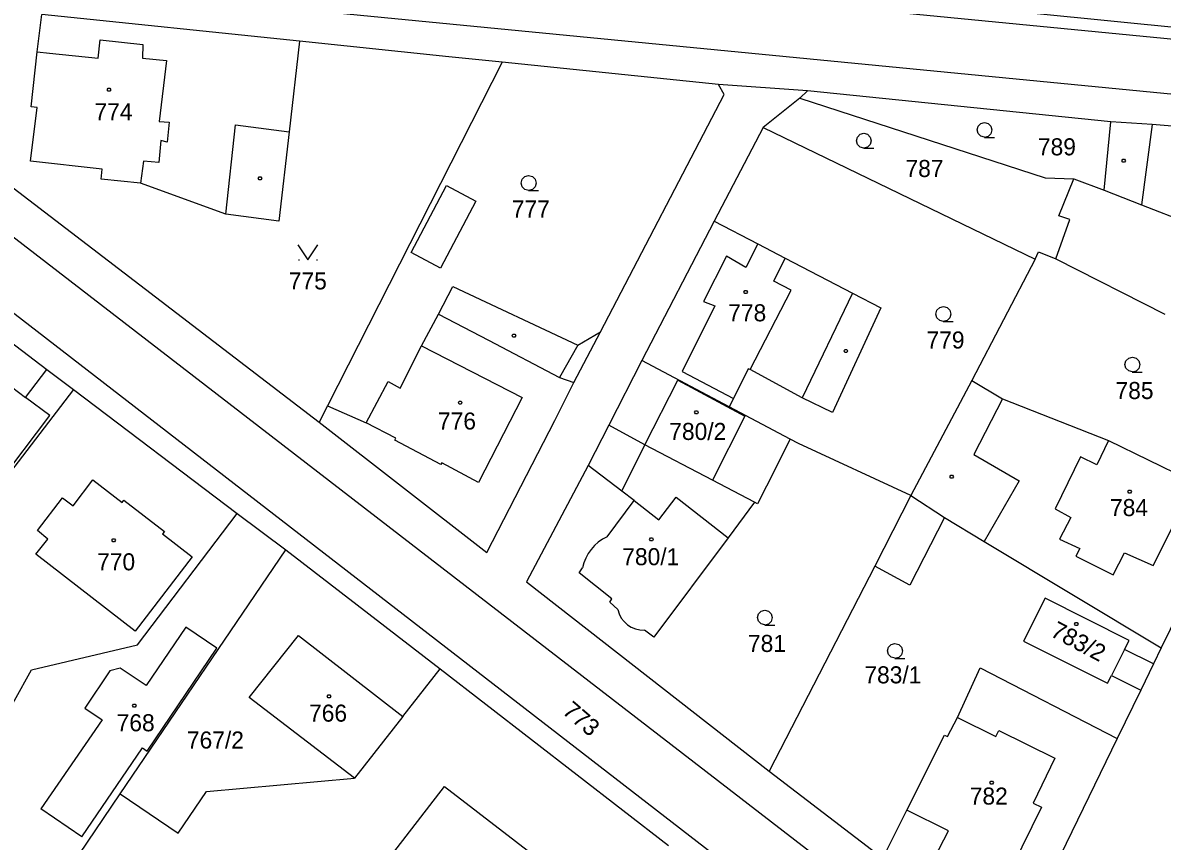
# Model space of a CAD drawing. Extents: x -621797 to -620972, y -1175539 to -1174697.
# Drawn here: x -621205.7 to -621092, y -1175212.1 to -1175130.5 of the extents above; entities that cross this region are included whole.
import ezdxf

# ---------------------------------------------------------------- set-up
doc = ezdxf.new("R2010")
doc.units = 0
for name, color, linetype in [('Rozvod plynu EON', 7, 'Continuous'), ('SDEL EON', 7, 'Continuous'), ('SDEL EON - popis', 7, 'Continuous'), ('Silnoproud EON', 7, 'Continuous'), ('Silnoproud EON - popis', 7, 'Continuous')]:
    doc.layers.add(name, color=color, linetype=linetype)

msp = doc.modelspace()

# ---------------------------------------------------------------- linework, layer by layer
at = {"layer": 'Rozvod plynu EON'}
for points in [[(-621196.98, -1175137.07), (-621196.89, -1175137.22), (-621196.98, -1175137.37), (-621197.16, -1175137.37), (-621197.25, -1175137.22), (-621197.16, -1175137.07)], [(-621095.77, -1175144.15), (-621095.68, -1175144.3), (-621095.77, -1175144.45), (-621095.95, -1175144.45), (-621096.04, -1175144.3), (-621095.95, -1175144.15)], [(-621181.93, -1175145.91), (-621181.84, -1175146.06), (-621181.93, -1175146.21), (-621182.11, -1175146.21), (-621182.2, -1175146.06), (-621182.11, -1175145.91)], [(-621133.48, -1175157.24), (-621133.39, -1175157.39), (-621133.48, -1175157.54), (-621133.66, -1175157.54), (-621133.75, -1175157.39), (-621133.66, -1175157.24)], [(-621156.6, -1175161.58), (-621156.51, -1175161.73), (-621156.6, -1175161.88), (-621156.78, -1175161.88), (-621156.87, -1175161.73), (-621156.78, -1175161.58)], [(-621123.49, -1175163.11), (-621123.4, -1175163.26), (-621123.49, -1175163.41), (-621123.67, -1175163.41), (-621123.76, -1175163.26), (-621123.67, -1175163.11)], [(-621161.96, -1175168.28), (-621161.87, -1175168.43), (-621161.96, -1175168.58), (-621162.14, -1175168.58), (-621162.23, -1175168.43), (-621162.14, -1175168.28)], [(-621138.39, -1175169.23), (-621138.3, -1175169.38), (-621138.39, -1175169.53), (-621138.57, -1175169.53), (-621138.66, -1175169.38), (-621138.57, -1175169.23)], [(-621112.94, -1175175.66), (-621112.85, -1175175.81), (-621112.94, -1175175.96), (-621113.12, -1175175.96), (-621113.21, -1175175.81), (-621113.12, -1175175.66)], [(-621095.19, -1175177.13), (-621095.1, -1175177.28), (-621095.19, -1175177.43), (-621095.37, -1175177.43), (-621095.46, -1175177.28), (-621095.37, -1175177.13)], [(-621196.52, -1175181.99), (-621196.43, -1175182.14), (-621196.52, -1175182.29), (-621196.7, -1175182.29), (-621196.79, -1175182.14), (-621196.7, -1175181.99)], [(-621142.88, -1175181.9), (-621142.79, -1175182.05), (-621142.88, -1175182.2), (-621143.06, -1175182.2), (-621143.15, -1175182.05), (-621143.06, -1175181.9)], [(-621100.5, -1175190.35), (-621100.41, -1175190.5), (-621100.5, -1175190.65), (-621100.68, -1175190.65), (-621100.77, -1175190.5), (-621100.68, -1175190.35)], [(-621175.04, -1175197.57), (-621174.95, -1175197.72), (-621175.04, -1175197.87), (-621175.22, -1175197.87), (-621175.31, -1175197.72), (-621175.22, -1175197.57)], [(-621194.45, -1175198.48), (-621194.36, -1175198.63), (-621194.45, -1175198.78), (-621194.63, -1175198.78), (-621194.72, -1175198.63), (-621194.63, -1175198.48)], [(-621108.95, -1175206.16), (-621108.86, -1175206.31), (-621108.95, -1175206.46), (-621109.13, -1175206.46), (-621109.22, -1175206.31), (-621109.13, -1175206.16)]]:
    msp.add_lwpolyline(points, close=True, dxfattribs=at)
at = {"layer": 'SDEL EON'}
for p, q in [((-621178.19, -1175154.18), (-621178.09, -1175154.18)), ((-621176.39, -1175154.18), (-621176.29, -1175154.18))]:
    msp.add_line(p, q, dxfattribs=at)
for points in [[(-621109.74, -1175141.96), (-621110.12, -1175141.86), (-621110.39, -1175141.59), (-621110.49, -1175141.22), (-621110.39, -1175140.85), (-621110.12, -1175140.58), (-621109.75, -1175140.48), (-621109.38, -1175140.58), (-621109.11, -1175140.85), (-621109.01, -1175141.23), (-621109.11, -1175141.61), (-621109.38, -1175141.88), (-621109.76, -1175141.98), (-621108.76, -1175141.98)], [(-621121.78, -1175143.04), (-621122.16, -1175142.94), (-621122.43, -1175142.67), (-621122.53, -1175142.3), (-621122.43, -1175141.93), (-621122.16, -1175141.66), (-621121.79, -1175141.56), (-621121.42, -1175141.66), (-621121.15, -1175141.93), (-621121.05, -1175142.31), (-621121.15, -1175142.69), (-621121.42, -1175142.96), (-621121.8, -1175143.06), (-621120.8, -1175143.06)], [(-621155.21, -1175147.26), (-621155.59, -1175147.16), (-621155.86, -1175146.89), (-621155.96, -1175146.52), (-621155.86, -1175146.15), (-621155.59, -1175145.88), (-621155.22, -1175145.78), (-621154.85, -1175145.88), (-621154.58, -1175146.15), (-621154.48, -1175146.53), (-621154.58, -1175146.91), (-621154.85, -1175147.18), (-621155.23, -1175147.28), (-621154.23, -1175147.28)], [(-621178.24, -1175152.68), (-621177.24, -1175154.18), (-621176.24, -1175152.68)], [(-621113.84, -1175160.32), (-621114.22, -1175160.22), (-621114.49, -1175159.95), (-621114.59, -1175159.58), (-621114.49, -1175159.21), (-621114.22, -1175158.94), (-621113.85, -1175158.84), (-621113.48, -1175158.94), (-621113.21, -1175159.21), (-621113.11, -1175159.59), (-621113.21, -1175159.97), (-621113.48, -1175160.24), (-621113.86, -1175160.34), (-621112.86, -1175160.34)], [(-621094.99, -1175165.36), (-621095.37, -1175165.26), (-621095.64, -1175164.99), (-621095.74, -1175164.62), (-621095.64, -1175164.25), (-621095.37, -1175163.98), (-621095, -1175163.88), (-621094.63, -1175163.98), (-621094.36, -1175164.25), (-621094.26, -1175164.63), (-621094.36, -1175165.01), (-621094.63, -1175165.28), (-621095.01, -1175165.38), (-621094.01, -1175165.38)], [(-621131.65, -1175190.58), (-621132.03, -1175190.48), (-621132.3, -1175190.21), (-621132.4, -1175189.84), (-621132.3, -1175189.47), (-621132.03, -1175189.2), (-621131.66, -1175189.1), (-621131.29, -1175189.2), (-621131.02, -1175189.47), (-621130.92, -1175189.85), (-621131.02, -1175190.23), (-621131.29, -1175190.5), (-621131.67, -1175190.6), (-621130.67, -1175190.6)], [(-621118.67, -1175193.91), (-621119.05, -1175193.81), (-621119.32, -1175193.54), (-621119.42, -1175193.17), (-621119.32, -1175192.8), (-621119.05, -1175192.53), (-621118.68, -1175192.43), (-621118.31, -1175192.53), (-621118.04, -1175192.8), (-621117.94, -1175193.18), (-621118.04, -1175193.56), (-621118.31, -1175193.83), (-621118.69, -1175193.93), (-621117.69, -1175193.93)]]:
    msp.add_lwpolyline(points, dxfattribs=at)
at = {"layer": 'SDEL EON - popis'}
for p, q in [((-621197.6, -1175121.77), (-621081.88, -1175133.05)), ((-621082.31, -1175138.52), (-621199.05, -1175127.17)), ((-621198.16, -1175134.08), (-621197.97, -1175132.25)), ((-621197.97, -1175132.25), (-621193.69, -1175132.7)), ((-621204.25, -1175133.44), (-621203, -1175133.57)), ((-621193.69, -1175132.7), (-621193.74, -1175134.06)), ((-621203, -1175133.57), (-621198.16, -1175134.08)), ((-621193.74, -1175134.06), (-621191.34, -1175134.31)), ((-621191.34, -1175134.31), (-621192.06, -1175140.38)), ((-621192.06, -1175140.38), (-621191.08, -1175140.46)), ((-621191.08, -1175140.46), (-621191.28, -1175142.45)), ((-621185.43, -1175149.61), (-621184.45, -1175140.72)), ((-621184.45, -1175140.72), (-621179.09, -1175141.41)), ((-621093.04, -1175140.67), (-621094.1, -1175148.7)), ((-621191.92, -1175142.28), (-621192.12, -1175144.47)), ((-621191.28, -1175142.45), (-621191.92, -1175142.28)), ((-621193.62, -1175144.34), (-621193.93, -1175146.55)), ((-621192.12, -1175144.47), (-621193.62, -1175144.34)), ((-621166.95, -1175153.44), (-621163.42, -1175146.78)), ((-621163.42, -1175146.78), (-621160.48, -1175148.34)), ((-621160.48, -1175148.34), (-621164.01, -1175155)), ((-621208, -1175150.85), (-621101.85, -1175232.68)), ((-621132.35, -1175152.58), (-621133.54, -1175154.94)), ((-621164.01, -1175155), (-621166.95, -1175153.44)), ((-621135.5, -1175153.8), (-621137.78, -1175158.33)), ((-621133.54, -1175154.94), (-621135.5, -1175153.8)), ((-621130.77, -1175156.32), (-621129.62, -1175154.01)), ((-621089.77, -1175249.76), (-621211.57, -1175155.68)), ((-621133.12, -1175165.13), (-621129.03, -1175157.19)), ((-621129.03, -1175157.19), (-621130.77, -1175156.32)), ((-621137.78, -1175158.33), (-621136.64, -1175158.77)), ((-621122.92, -1175157.49), (-621127.94, -1175167.95)), ((-621164.22, -1175159.59), (-621159.23, -1175162.19)), ((-621136.64, -1175158.77), (-621139.92, -1175165.3)), ((-621165.91, -1175162.75), (-621155.88, -1175167.92)), ((-621159.23, -1175162.19), (-621152.13, -1175165.9)), ((-621150.31, -1175162.69), (-621152.13, -1175165.9)), ((-621211.01, -1175163.66), (-621205.39, -1175167.9)), ((-621205.39, -1175167.9), (-621203.27, -1175165.11)), ((-621139.92, -1175165.3), (-621134.8, -1175167.99)), ((-621152.13, -1175165.9), (-621150.71, -1175166.41)), ((-621143.62, -1175172.63), (-621140.35, -1175166.18)), ((-621140.35, -1175166.18), (-621133.67, -1175169.76)), ((-621202.99, -1175169.71), (-621205.39, -1175167.9)), ((-621155.88, -1175167.92), (-621160.21, -1175176.39)), ((-621107.97, -1175168.05), (-621110.83, -1175173.59)), ((-621210.34, -1175179.44), (-621202.99, -1175169.71)), ((-621133.67, -1175169.76), (-621136.87, -1175176.14)), ((-621168.46, -1175171.97), (-621171.43, -1175170.44)), ((-621168.55, -1175172.16), (-621168.46, -1175171.97)), ((-621163.99, -1175174.6), (-621168.55, -1175172.16)), ((-621145.94, -1175177.23), (-621143.62, -1175172.63)), ((-621097.38, -1175172.19), (-621098.56, -1175174.62)), ((-621163.88, -1175174.41), (-621163.99, -1175174.6)), ((-621160.21, -1175176.39), (-621163.88, -1175174.41)), ((-621110.83, -1175173.59), (-621106.3, -1175176.2)), ((-621100.18, -1175173.83), (-621102.7, -1175179.02)), ((-621098.56, -1175174.62), (-621100.18, -1175173.83)), ((-621106.3, -1175176.2), (-621109.79, -1175182.26)), ((-621144.69, -1175178.19), (-621142.22, -1175180.12)), ((-621142.22, -1175180.12), (-621140.52, -1175177.86)), ((-621140.52, -1175177.86), (-621135.33, -1175181.89)), ((-621113.74, -1175179.87), (-621117.21, -1175186.62)), ((-621102.7, -1175179.02), (-621101.13, -1175179.87)), ((-621101.13, -1175179.87), (-621102.26, -1175182.04)), ((-621092.93, -1175184.65), (-621091.04, -1175180.89)), ((-621102.26, -1175182.04), (-621100.25, -1175182.96)), ((-621100.25, -1175182.96), (-621100.63, -1175183.74)), ((-621096.92, -1175185.58), (-621095.8, -1175183.39)), ((-621095.8, -1175183.39), (-621092.93, -1175184.65)), ((-621100.63, -1175183.74), (-621096.92, -1175185.58)), ((-621117.21, -1175186.62), (-621120.69, -1175184.73)), ((-621095.78, -1175193.04), (-621097.09, -1175195.62)), ((-621112.43, -1175199.81), (-621108.61, -1175201.7)), ((-621108.61, -1175201.7), (-621108.31, -1175201.12)), ((-621108.31, -1175201.12), (-621102.72, -1175203.88)), ((-621102.72, -1175203.88), (-621104.9, -1175208.35)), ((-621104.9, -1175208.35), (-621104.06, -1175208.76)), ((-621113.35, -1175211.13), (-621117.5, -1175209.07)), ((-621104.06, -1175208.76), (-621107.98, -1175216.73)), ((-621114.77, -1175213.88), (-621113.35, -1175211.13))]:
    msp.add_line(p, q, dxfattribs=at)
at = {"layer": 'Silnoproud EON'}
for p, q in [((-621147.63, -1175125.29), (-621085.82, -1175131.48)), ((-621204.25, -1175133.44), (-621203.79, -1175129.72)), ((-621178.07, -1175132.39), (-621203.79, -1175129.72)), ((-621204.83, -1175138.91), (-621204.25, -1175133.44)), ((-621178.07, -1175132.39), (-621179.09, -1175141.41)), ((-621163.19, -1175133.92), (-621178.07, -1175132.39)), ((-621157.87, -1175134.47), (-621175.27, -1175168.73)), ((-621157.87, -1175134.47), (-621163.19, -1175133.92)), ((-621136.29, -1175136.69), (-621157.87, -1175134.47)), ((-621127.39, -1175137.34), (-621136.29, -1175136.69)), ((-621135.71, -1175137.7), (-621136.29, -1175136.69)), ((-621148.06, -1175161.35), (-621135.71, -1175137.7)), ((-621127.39, -1175137.34), (-621128.18, -1175138.06)), ((-621097.16, -1175140.41), (-621127.39, -1175137.34)), ((-621204.91, -1175144.35), (-621204.25, -1175138.98)), ((-621204.25, -1175138.98), (-621204.83, -1175138.91)), ((-621128.18, -1175138.06), (-621131.84, -1175140.97)), ((-621128.18, -1175138.06), (-621103.71, -1175146)), ((-621179.09, -1175141.41), (-621180.14, -1175150.33)), ((-621131.84, -1175140.97), (-621136.7, -1175150.32)), ((-621131.84, -1175140.97), (-621104.71, -1175154.11)), ((-621097.83, -1175147.23), (-621097.16, -1175140.41)), ((-621093.04, -1175140.67), (-621097.16, -1175140.41)), ((-621072.86, -1175142.5), (-621093.04, -1175140.67)), ((-621213.76, -1175141.57), (-621176.1, -1175170.37)), ((-621197.76, -1175145.13), (-621204.91, -1175144.35)), ((-621197.87, -1175146.14), (-621197.76, -1175145.13)), ((-621103.71, -1175146), (-621100.85, -1175146.09)), ((-621193.93, -1175146.55), (-621197.87, -1175146.14)), ((-621185.43, -1175149.61), (-621193.93, -1175146.55)), ((-621102.32, -1175149.8), (-621100.85, -1175146.09)), ((-621100.85, -1175146.09), (-621097.83, -1175147.23)), ((-621097.83, -1175147.23), (-621094.1, -1175148.7)), ((-621094.1, -1175148.7), (-621087.48, -1175151.29)), ((-621180.14, -1175150.33), (-621185.43, -1175149.61)), ((-621136.7, -1175150.32), (-621143.93, -1175164.22)), ((-621136.7, -1175150.32), (-621132.35, -1175152.58)), ((-621102.64, -1175154.09), (-621101.25, -1175150.15)), ((-621101.25, -1175150.15), (-621102.32, -1175149.8)), ((-621132.35, -1175152.58), (-621129.62, -1175154.01)), ((-621104.71, -1175154.11), (-621104.38, -1175153.38)), ((-621104.38, -1175153.38), (-621102.64, -1175154.09)), ((-621129.62, -1175154.01), (-621122.92, -1175157.49)), ((-621104.71, -1175154.11), (-621111.01, -1175166.21)), ((-621102.64, -1175154.09), (-621091.76, -1175159.6)), ((-621164.22, -1175159.59), (-621162.78, -1175156.84)), ((-621162.78, -1175156.84), (-621150.31, -1175162.69)), ((-621122.92, -1175157.49), (-621120.09, -1175158.96)), ((-621165.91, -1175162.75), (-621164.22, -1175159.59)), ((-621120.09, -1175158.96), (-621124.92, -1175169.39)), ((-621208.88, -1175160.86), (-621203.27, -1175165.11)), ((-621150.71, -1175166.41), (-621148.06, -1175161.35)), ((-621150.31, -1175162.69), (-621148.06, -1175161.35)), ((-621168.05, -1175166.97), (-621165.91, -1175162.75)), ((-621203.27, -1175165.11), (-621200.63, -1175167.11)), ((-621143.93, -1175164.22), (-621147.22, -1175170.66)), ((-621135.21, -1175168.82), (-621143.93, -1175164.22)), ((-621133.31, -1175165.05), (-621134.8, -1175167.99)), ((-621133.12, -1175165.13), (-621133.31, -1175165.05)), ((-621127.94, -1175167.95), (-621133.12, -1175165.13)), ((-621171.43, -1175170.44), (-621169.24, -1175166.31)), ((-621169.24, -1175166.31), (-621168.05, -1175166.97)), ((-621152.59, -1175170.21), (-621150.71, -1175166.41)), ((-621111.01, -1175166.21), (-621117.09, -1175177.68)), ((-621111.01, -1175166.21), (-621107.97, -1175168.05)), ((-621200.63, -1175167.11), (-621209.09, -1175178.17)), ((-621200.63, -1175167.11), (-621184.3, -1175179.48)), ((-621175.27, -1175168.73), (-621176.1, -1175170.37)), ((-621175.27, -1175168.73), (-621171.43, -1175170.44)), ((-621134.8, -1175167.99), (-621135.21, -1175168.82)), ((-621124.92, -1175169.39), (-621127.94, -1175167.95)), ((-621107.97, -1175168.05), (-621097.38, -1175172.19)), ((-621129.15, -1175172.05), (-621135.21, -1175168.82)), ((-621176.1, -1175170.37), (-621159.4, -1175183.35)), ((-621159.4, -1175183.35), (-621152.59, -1175170.21)), ((-621147.22, -1175170.66), (-621149.28, -1175174.68)), ((-621143.62, -1175172.63), (-621147.22, -1175170.66)), ((-621129.15, -1175172.05), (-621131.5, -1175176.76)), ((-621128.3, -1175172.48), (-621129.15, -1175172.05)), ((-621136.87, -1175176.14), (-621143.62, -1175172.63)), ((-621117.09, -1175177.68), (-621128.3, -1175172.48)), ((-621097.38, -1175172.19), (-621088.62, -1175176.48)), ((-621149.28, -1175174.68), (-621155.43, -1175186.28)), ((-621145.94, -1175177.23), (-621149.28, -1175174.68)), ((-621200.65, -1175178.71), (-621198.7, -1175176.11)), ((-621198.7, -1175176.11), (-621195.76, -1175178.37)), ((-621132.69, -1175178.35), (-621136.87, -1175176.14)), ((-621144.69, -1175178.19), (-621145.94, -1175177.23)), ((-621131.5, -1175176.76), (-621132.38, -1175178.52)), ((-621117.09, -1175177.68), (-621120.69, -1175184.73)), ((-621117.09, -1175177.68), (-621113.74, -1175179.87)), ((-621204.22, -1175181.16), (-621201.71, -1175177.92)), ((-621201.71, -1175177.92), (-621200.65, -1175178.71)), ((-621195.76, -1175178.37), (-621195.58, -1175178.13)), ((-621195.58, -1175178.13), (-621191.55, -1175181.26)), ((-621147.4, -1175181.8), (-621144.69, -1175178.19)), ((-621132.69, -1175178.35), (-621135.33, -1175181.89)), ((-621132.38, -1175178.52), (-621132.69, -1175178.35)), ((-621085.03, -1175178.33), (-621092.13, -1175192.87)), ((-621194.24, -1175192.58), (-621184.3, -1175179.48)), ((-621184.3, -1175179.48), (-621179.43, -1175183.08)), ((-621113.74, -1175179.87), (-621109.79, -1175182.26)), ((-621203.16, -1175182.02), (-621204.22, -1175181.16)), ((-621204.37, -1175183.52), (-621203.16, -1175182.02)), ((-621191.55, -1175181.26), (-621191.74, -1175181.5)), ((-621191.74, -1175181.5), (-621188.77, -1175183.79)), ((-621135.33, -1175181.89), (-621142.73, -1175191.79)), ((-621109.79, -1175182.26), (-621092.13, -1175192.87)), ((-621195.95, -1175207.41), (-621179.43, -1175183.08)), ((-621179.43, -1175183.08), (-621164.04, -1175194.97)), ((-621194.46, -1175191.19), (-621204.37, -1175183.52)), ((-621188.77, -1175183.79), (-621194.46, -1175191.19)), ((-621150.18, -1175185.38), (-621149.84, -1175184.89)), ((-621146.92, -1175187.98), (-621150.18, -1175185.38)), ((-621120.69, -1175184.73), (-621131.22, -1175205.15)), ((-621155.43, -1175186.28), (-621131.22, -1175205.15)), ((-621147.13, -1175188.33), (-621146.92, -1175187.98)), ((-621103.69, -1175187.91), (-621105.86, -1175192.19)), ((-621095.33, -1175192.15), (-621103.69, -1175187.91)), ((-621146.33, -1175189.04), (-621147.13, -1175188.33)), ((-621189.42, -1175190.81), (-621193.37, -1175196.64)), ((-621186.32, -1175192.91), (-621189.42, -1175190.81)), ((-621142.73, -1175191.79), (-621143.65, -1175191.1)), ((-621204.82, -1175195.05), (-621194.24, -1175192.58)), ((-621183.11, -1175197.81), (-621178.19, -1175191.63)), ((-621178.19, -1175191.63), (-621167.76, -1175199.71)), ((-621105.86, -1175192.19), (-621097.47, -1175196.38)), ((-621095.78, -1175193.04), (-621095.33, -1175192.15)), ((-621193.26, -1175203.18), (-621186.32, -1175192.91)), ((-621092.91, -1175194.47), (-621095.78, -1175193.04)), ((-621092.13, -1175192.87), (-621092.91, -1175194.47)), ((-621112.43, -1175199.81), (-621110.19, -1175194.87)), ((-621110.19, -1175194.87), (-621096.51, -1175201.92)), ((-621092.91, -1175194.47), (-621094.17, -1175197.08)), ((-621224.04, -1175229.72), (-621204.82, -1175195.05)), ((-621196.99, -1175195.16), (-621199.47, -1175198.88)), ((-621195.96, -1175194.89), (-621196.99, -1175195.16)), ((-621193.37, -1175196.64), (-621195.96, -1175194.89)), ((-621167.76, -1175199.71), (-621164.04, -1175194.97)), ((-621164.04, -1175194.97), (-621141.26, -1175212.57)), ((-621097.47, -1175196.38), (-621097.09, -1175195.62)), ((-621097.09, -1175195.62), (-621094.17, -1175197.08)), ((-621094.17, -1175197.08), (-621096.51, -1175201.92)), ((-621172.59, -1175205.88), (-621183.11, -1175197.81)), ((-621199.47, -1175198.88), (-621197.77, -1175200.04)), ((-621197.77, -1175200.04), (-621203.86, -1175208.91)), ((-621167.76, -1175199.71), (-621172.59, -1175205.88)), ((-621113.43, -1175201.72), (-621112.43, -1175199.81)), ((-621117.5, -1175209.07), (-621113.75, -1175201.56)), ((-621113.75, -1175201.56), (-621113.43, -1175201.72)), ((-621096.51, -1175201.92), (-621106.57, -1175222.57)), ((-621199.79, -1175211.73), (-621193.75, -1175202.84)), ((-621193.75, -1175202.84), (-621193.26, -1175203.18)), ((-621187.34, -1175207.2), (-621172.59, -1175205.88)), ((-621131.22, -1175205.15), (-621119.89, -1175213.84)), ((-621190.16, -1175211.34), (-621187.34, -1175207.2)), ((-621172.9, -1175218.73), (-621163.62, -1175206.69)), ((-621163.62, -1175206.69), (-621148.24, -1175218.52)), ((-621218.73, -1175240.96), (-621195.95, -1175207.41)), ((-621195.95, -1175207.41), (-621190.16, -1175211.34)), ((-621199.79, -1175211.73), (-621203.86, -1175208.91)), ((-621119.89, -1175213.84), (-621117.5, -1175209.07))]:
    msp.add_line(p, q, dxfattribs=at)
for centre, radius, start, end in [((-621145.538, -1175185.779), 4.393, 115.08039, 168.32727), ((-621143.775, -1175188.49), 2.613, 192.15758, 272.74657)]:
    msp.add_arc(centre, radius, start, end, dxfattribs=at)

# ---------------------------------------------------------------- texts
at = {"layer": 'Silnoproud EON - popis'}
for s, p in [('774', (-621198.523, -1175140.26)), ('789', (-621104.423, -1175143.76)), ('787', (-621117.633, -1175145.92)), ('777', (-621156.903, -1175149.96)), ('775', (-621179.143, -1175157.13)), ('778', (-621135.313, -1175160.31)), ('779', (-621115.533, -1175163.02)), ('785', (-621096.683, -1175168.06)), ('776', (-621164.263, -1175171.1)), ('780/2', (-621141.193, -1175172.14)), ('784', (-621097.233, -1175179.73)), ('770', (-621198.263, -1175185.14)), ('780/1', (-621145.883, -1175184.63)), ('781', (-621133.343, -1175193.28)), ('783/1', (-621121.733, -1175196.41)), ('766', (-621177.123, -1175200.23)), ('768', (-621196.313, -1175201.19)), ('767/2', (-621189.306, -1175202.91)), ('782', (-621111.223, -1175208.5))]:
    msp.add_text(s, height=1.7, dxfattribs=at).set_placement(p)
for s, rotation, p in [('783/2', 332.08634, (-621103.28, -1175191.641)), ('773', 319.48127, (-621151.95, -1175199.344))]:
    msp.add_text(s, height=1.7, rotation=rotation, dxfattribs=at).set_placement(p)

doc.saveas('drawing.dxf')
